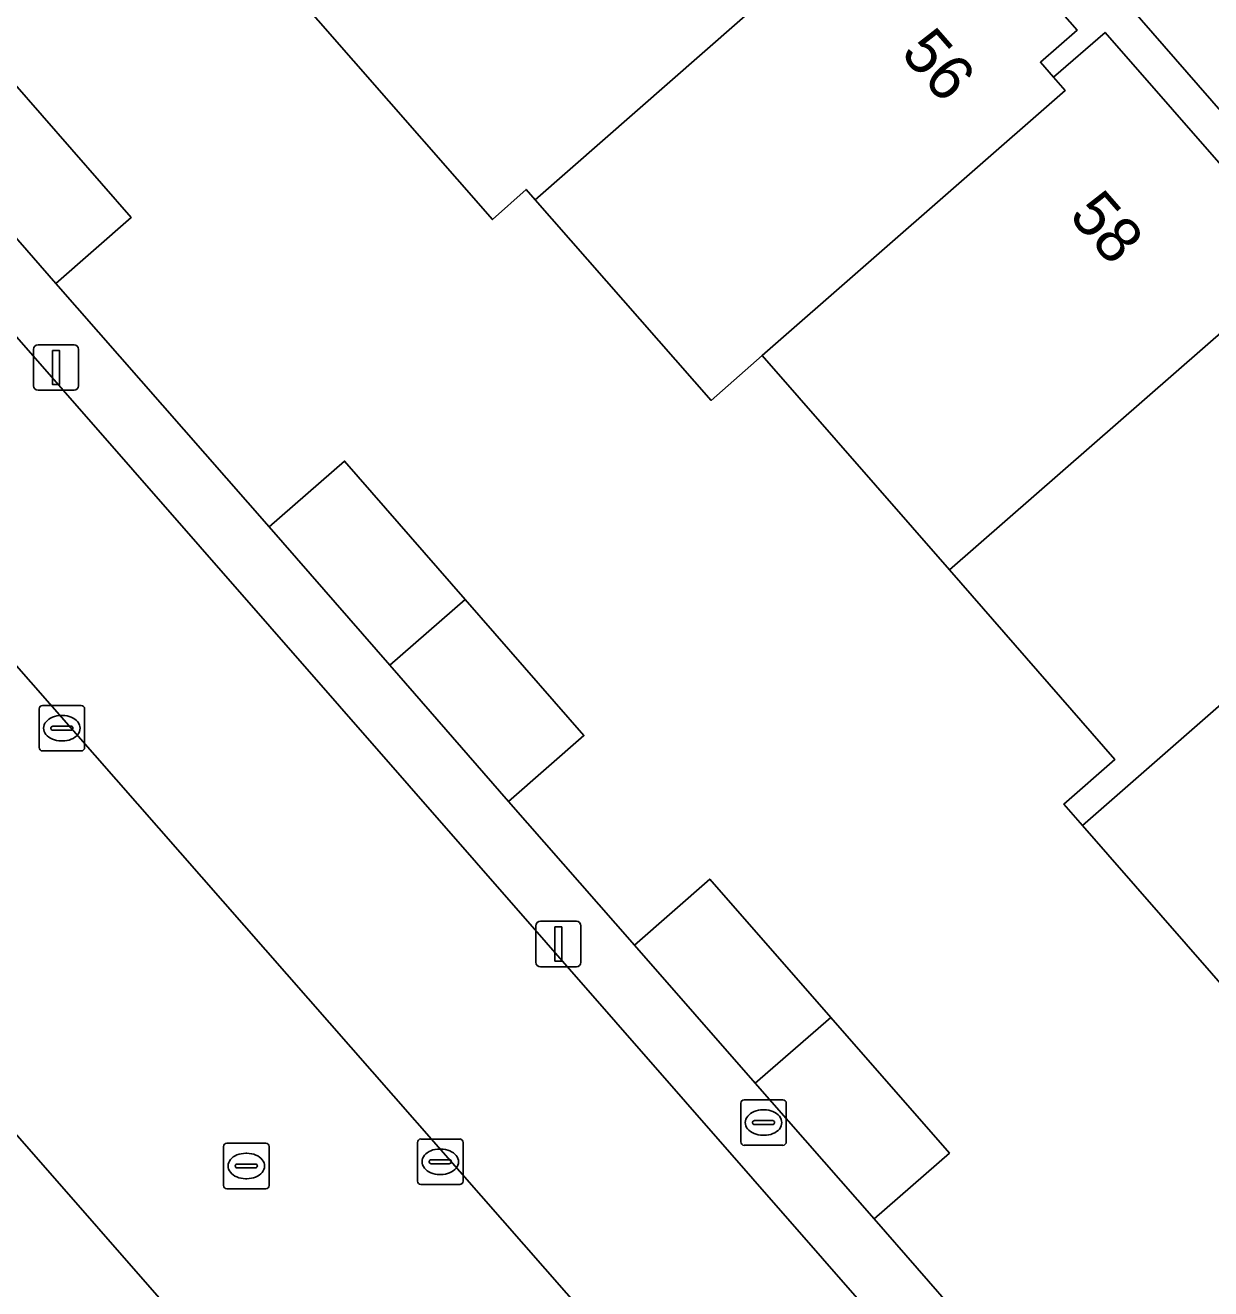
# Model space of a CAD drawing. Extents: x 161772 to 163126, y 383092 to 383917.
# Drawn here: x 162246.89 to 162272.95, y 383264.29 to 383292.04 of the extents above; entities that cross this region are included whole.
import ezdxf

# ---------------------------------------------------------------- set-up
doc = ezdxf.new("R2010")
doc.units = 0
for name, color, linetype in [('IMGEO_Erf', 7, 'Continuous'), ('IMGEO_Kolk', 7, 'Continuous'), ('IMGEO_Lichtmast', 7, 'Continuous'), ('IMGEO_Muur', 7, 'Continuous'), ('IMGEO_Pand', 7, 'Continuous'), ('IMGEO_Pand_nummerreeks', 7, 'Continuous'), ('IMGEO_Parkeervlak_gesloten', 7, 'Continuous'), ('IMGEO_Rijbaan_lokaal_gesloten', 7, 'Continuous'), ('IMGEO_Rioolput', 7, 'Continuous'), ('IMGEO_Voetpad_open', 7, 'Continuous')]:
    doc.layers.add(name, color=color, linetype=linetype)

msp = doc.modelspace()

# ---------------------------------------------------------------- linework, layer by layer
at = {"layer": 'IMGEO_Erf'}
for points in [[(162295.504, 383264.551), (162257.559, 383308.056)], [(162274.128, 383269.89), (162270.126, 383274.467), (162269.719, 383274.933), (162270.84, 383275.914), (162267.201, 383280.079), (162263.083, 383284.79), (162261.968, 383283.801), (162258.1, 383288.208), (162257.898, 383288.439), (162257.156, 383287.777), (162251.05, 383294.755)], [(162268.224, 383293.976), (162270.009, 383291.937), (162269.203, 383291.233), (162269.493, 383290.901), (162270.622, 383291.889), (162273.586, 383288.503)], [(162246.607, 383290.81), (162249.22, 383287.823), (162247.564, 383286.375), (162252.251, 383281.024), (162253.909, 383282.47), (162256.561, 383279.43), (162259.169, 383276.44), (162257.511, 383274.994), (162260.28, 383271.838), (162261.936, 383273.287), (162264.597, 383270.246), (162267.203, 383267.268), (162265.548, 383265.819), (162268.386, 383262.574), (162270.042, 383264.022), (162272.687, 383260.996), (162275.311, 383257.995)]]:
    msp.add_lwpolyline(points, dxfattribs=at)
at = {"layer": 'IMGEO_Kolk'}
for p, q in [((162247.194, 383276.175), (162247.194, 383277.027)), ((162247.269, 383277.101), (162248.121, 383277.101)), ((162248.195, 383277.027), (162248.195, 383276.175)), ((162247.682, 383276.881), (162247.707, 383276.881)), ((162247.453, 383276.595), (162247.453, 383276.607)), ((162247.891, 383276.558), (162247.493, 383276.558)), ((162247.496, 383276.644), (162247.894, 383276.644)), ((162247.937, 383276.607), (162247.937, 383276.595)), ((162247.705, 383276.321), (162247.68, 383276.321)), ((162248.121, 383276.101), (162247.269, 383276.101)), ((162262.691, 383268.437), (162263.543, 383268.437)), ((162262.616, 383267.511), (162262.616, 383268.363)), ((162263.104, 383268.217), (162263.129, 383268.217)), ((162263.617, 383268.363), (162263.617, 383267.511)), ((162262.875, 383267.931), (162262.875, 383267.943)), ((162263.313, 383267.894), (162262.915, 383267.894)), ((162262.918, 383267.98), (162263.316, 383267.98)), ((162263.359, 383267.943), (162263.359, 383267.931)), ((162263.127, 383267.657), (162263.102, 383267.657)), ((162255.511, 383266.65), (162255.511, 383267.502)), ((162255.586, 383267.576), (162256.438, 383267.576)), ((162255.999, 383267.356), (162256.024, 383267.356)), ((162256.512, 383267.502), (162256.512, 383266.65)), ((162263.543, 383267.437), (162262.691, 383267.437)), ((162255.77, 383267.07), (162255.77, 383267.082)), ((162256.208, 383267.033), (162255.81, 383267.033)), ((162255.813, 383267.119), (162256.211, 383267.119)), ((162256.254, 383267.082), (162256.254, 383267.07)), ((162256.022, 383266.796), (162255.997, 383266.796)), ((162256.438, 383266.576), (162255.586, 383266.576))]:
    msp.add_line(p, q, dxfattribs=at)
for points in [[(162247.194, 383276.175), (162247.194, 383277.027)], [(162247.269, 383277.101), (162248.121, 383277.101)], [(162248.195, 383277.027), (162248.195, 383276.175)], [(162248.121, 383276.101), (162247.269, 383276.101)], [(162262.691, 383268.437), (162263.543, 383268.437)], [(162262.616, 383267.511), (162262.616, 383268.363)], [(162263.617, 383268.363), (162263.617, 383267.511)], [(162255.511, 383266.65), (162255.511, 383267.502)], [(162255.586, 383267.576), (162256.438, 383267.576)], [(162256.512, 383267.502), (162256.512, 383266.65)], [(162263.543, 383267.437), (162262.691, 383267.437)], [(162256.438, 383266.576), (162255.586, 383266.576)]]:
    msp.add_lwpolyline(points, dxfattribs=at)
for centre, radius, start, end in [((162247.271, 383277.025), 0.0765, 91.552, 178.448), ((162247.271, 383277.025), 0.0765, 91.552, 178.448), ((162248.119, 383277.025), 0.0765, 1.552, 88.448), ((162248.119, 383277.025), 0.0765, 1.552, 88.448), ((162247.493, 383276.604), 0.0403, 85.8775, 175.7526), ((162247.49, 383276.594), 0.0366, 178.938, 274.7102), ((162247.894, 383276.601), 0.043, 264.8664, 352.4533), ((162247.898, 383276.606), 0.0386, 1.7309, 96.639), ((162247.271, 383276.177), 0.0765, 181.552, 268.448), ((162247.271, 383276.177), 0.0765, 181.552, 268.448), ((162248.119, 383276.177), 0.0765, 271.552, 358.448), ((162248.119, 383276.177), 0.0765, 271.552, 358.448), ((162262.693, 383268.361), 0.0765, 91.552, 178.448), ((162262.693, 383268.361), 0.0765, 91.552, 178.448), ((162263.541, 383268.361), 0.0765, 1.552, 88.448), ((162263.541, 383268.361), 0.0765, 1.552, 88.448), ((162262.915, 383267.94), 0.0403, 85.8775, 175.7526), ((162262.912, 383267.93), 0.0366, 178.938, 274.7102), ((162263.316, 383267.937), 0.043, 264.8664, 352.4533), ((162263.32, 383267.942), 0.0386, 1.7309, 96.639), ((162255.588, 383267.5), 0.0765, 91.552, 178.448), ((162255.588, 383267.5), 0.0765, 91.552, 178.448), ((162256.436, 383267.5), 0.0765, 1.552, 88.448), ((162256.436, 383267.5), 0.0765, 1.552, 88.448), ((162262.693, 383267.513), 0.0765, 181.552, 268.448), ((162262.693, 383267.513), 0.0765, 181.552, 268.448), ((162263.541, 383267.513), 0.0765, 271.552, 358.448), ((162263.541, 383267.513), 0.0765, 271.552, 358.448), ((162255.81, 383267.079), 0.0403, 85.8775, 175.7526), ((162255.807, 383267.069), 0.0366, 178.938, 274.7102), ((162256.211, 383267.076), 0.043, 264.8664, 352.4533), ((162256.215, 383267.081), 0.0386, 1.7309, 96.639), ((162255.588, 383266.652), 0.0765, 181.552, 268.448), ((162255.588, 383266.652), 0.0765, 181.552, 268.448), ((162256.436, 383266.652), 0.0765, 271.552, 358.448), ((162256.436, 383266.652), 0.0765, 271.552, 358.448)]:
    msp.add_arc(centre, radius, start, end, dxfattribs=at)
for centre, major_axis, ratio, start_param, end_param in [((162247.681, 383276.601), (-0.387, 0.002), 0.722429, 4.712389, 7.853982), ((162247.706, 383276.601), (-0.39, 0.002), 0.717154, 1.570796, 4.712389), ((162263.103, 383267.937), (-0.387, 0.002), 0.722429, 4.712389, 7.853982), ((162263.128, 383267.937), (-0.39, 0.002), 0.717154, 1.570796, 4.712389), ((162255.998, 383267.076), (-0.387, 0.002), 0.722429, 4.712389, 7.853982), ((162256.023, 383267.076), (-0.39, 0.002), 0.717154, 1.570796, 4.712389)]:
    msp.add_ellipse(centre, major_axis=major_axis, ratio=ratio, start_param=start_param, end_param=end_param, dxfattribs=at)
at = {"layer": 'IMGEO_Lichtmast'}
for p, q in [((162247.072, 383284.125), (162247.072, 383284.925)), ((162247.072, 383284.925), (162247.072, 383284.125)), ((162247.172, 383285.025), (162247.962, 383285.025)), ((162247.962, 383285.025), (162247.172, 383285.025)), ((162248.062, 383284.925), (162248.062, 383284.125)), ((162248.062, 383284.125), (162248.062, 383284.925)), ((162247.962, 383284.025), (162247.172, 383284.025)), ((162247.172, 383284.025), (162247.962, 383284.025)), ((162258.213, 383272.359), (162259.003, 383272.359)), ((162259.003, 383272.359), (162258.213, 383272.359)), ((162258.113, 383271.459), (162258.113, 383272.259)), ((162258.113, 383272.259), (162258.113, 383271.459)), ((162259.103, 383272.259), (162259.103, 383271.459)), ((162259.103, 383271.459), (162259.103, 383272.259)), ((162259.003, 383271.359), (162258.213, 383271.359)), ((162258.213, 383271.359), (162259.003, 383271.359))]:
    msp.add_line(p, q, dxfattribs=at)
for points in [[(162247.492, 383284.9), (162247.642, 383284.9), (162247.642, 383284.15), (162247.492, 383284.15), (162247.492, 383284.9)], [(162258.533, 383272.234), (162258.683, 383272.234), (162258.683, 383271.484), (162258.533, 383271.484), (162258.533, 383272.234)]]:
    msp.add_lwpolyline(points, dxfattribs=at)
for centre, start, end in [((162247.172, 383284.925), 90, 180), ((162247.172, 383284.925), 90, 180), ((162247.962, 383284.925), 0, 90), ((162247.962, 383284.925), 360, 90), ((162247.172, 383284.125), 180, 270), ((162247.172, 383284.125), 180, 270), ((162247.962, 383284.125), 270, 0), ((162247.962, 383284.125), 270, 0), ((162258.213, 383272.259), 90, 180), ((162258.213, 383272.259), 90, 180), ((162259.003, 383272.259), 0, 90), ((162259.003, 383272.259), 360, 90), ((162258.213, 383271.459), 180, 270), ((162258.213, 383271.459), 180, 270), ((162259.003, 383271.459), 270, 0), ((162259.003, 383271.459), 270, 0)]:
    msp.add_arc(centre, 0.1, start, end, dxfattribs=at)
at = {"layer": 'IMGEO_Muur'}
for points in [[(162252.251, 383281.024), (162247.564, 383286.375)], [(162260.28, 383271.838), (162257.511, 383274.994)], [(162268.386, 383262.574), (162265.548, 383265.819)]]:
    msp.add_lwpolyline(points, dxfattribs=at)
at = {"layer": 'IMGEO_Pand'}
for points in [[(162251.05, 383294.755), (162257.156, 383287.777), (162257.898, 383288.439), (162258.1, 383288.208), (162265.494, 383294.697), (162265.877, 383295.033), (162265.304, 383295.687), (162264.921, 383295.351), (162264.049, 383296.347), (162264.417, 383296.671), (162263.778, 383297.401), (162264.59, 383298.113), (162262.804, 383300.151), (162261.999, 383299.446), (162261.426, 383300.1), (162260.621, 383299.395), (162258.768, 383301.51)], [(162258.1, 383288.208), (162261.968, 383283.801), (162263.083, 383284.79), (162269.746, 383290.613), (162269.493, 383290.901), (162269.203, 383291.233), (162270.009, 383291.937), (162268.224, 383293.976), (162267.419, 383293.272), (162266.786, 383293.994), (162266.403, 383293.658), (162265.494, 383294.697)], [(162274.615, 383286.558), (162275, 383286.893), (162274.487, 383287.484), (162274.111, 383287.129), (162273.202, 383288.167), (162273.586, 383288.503), (162270.622, 383291.889), (162269.493, 383290.901), (162269.746, 383290.613), (162263.083, 383284.79), (162267.201, 383280.079)], [(162244.953, 383289.36), (162247.564, 383286.375), (162249.22, 383287.823), (162246.607, 383290.81)], [(162277.919, 383281.28), (162277.778, 383281.441), (162278.908, 383282.428), (162275.918, 383285.849), (162275.52, 383285.516), (162274.615, 383286.558), (162267.201, 383280.079), (162270.84, 383275.914), (162269.719, 383274.933), (162270.126, 383274.467)], [(162254.901, 383277.987), (162256.561, 383279.43), (162253.909, 383282.47), (162252.251, 383281.024)], [(162274.128, 383269.89), (162281.558, 383276.386), (162281.944, 383276.719), (162281.434, 383277.31), (162281.019, 383276.95), (162280.115, 383277.992), (162280.501, 383278.326), (162279.858, 383279.067), (162280.667, 383279.768), (162278.889, 383281.818), (162278.068, 383281.11), (162277.919, 383281.28), (162270.126, 383274.467)], [(162254.901, 383277.987), (162257.511, 383274.994), (162259.169, 383276.44), (162256.561, 383279.43)], [(162262.934, 383268.805), (162264.597, 383270.246), (162261.936, 383273.287), (162260.28, 383271.838)], [(162262.934, 383268.805), (162265.548, 383265.819), (162267.203, 383267.268), (162264.597, 383270.246)]]:
    msp.add_lwpolyline(points, close=True, dxfattribs=at)
at = {"layer": 'IMGEO_Parkeervlak_gesloten'}
for points in [[(162272.905, 383248.092), (162276.559, 383251.066), (162241.639, 383290.974), (162238.045, 383287.827)], [(162232.95, 383283.366), (162229.559, 383280.396), (162247.626, 383259.685), (162251.061, 383262.68)]]:
    msp.add_lwpolyline(points, close=True, dxfattribs=at)
at = {"layer": 'IMGEO_Rijbaan_lokaal_gesloten'}
msp.add_lwpolyline([(162251.061, 383262.68), (162252.791, 383260.692), (162249.275, 383257.833), (162248.076, 383256.871), (162241.074, 383251.163), (162244.227, 383247.286), (162252.554, 383254.049), (162256.096, 383256.95), (162257.613, 383255.216), (162267.579, 383243.756), (162272.905, 383248.092), (162238.045, 383287.827), (162232.95, 383283.366)], close=True, dxfattribs=at)
at = {"layer": 'IMGEO_Rioolput'}
for p, q in [((162251.248, 383266.557), (162251.248, 383267.409)), ((162251.323, 383267.483), (162252.175, 383267.483)), ((162252.249, 383267.409), (162252.249, 383266.557)), ((162251.736, 383267.263), (162251.761, 383267.263)), ((162251.507, 383266.977), (162251.507, 383266.989)), ((162251.945, 383266.94), (162251.547, 383266.94)), ((162251.55, 383267.026), (162251.948, 383267.026)), ((162251.991, 383266.989), (162251.991, 383266.977)), ((162252.175, 383266.483), (162251.323, 383266.483)), ((162251.759, 383266.703), (162251.734, 383266.703))]:
    msp.add_line(p, q, dxfattribs=at)
for points in [[(162251.248, 383266.557), (162251.248, 383267.409)], [(162251.323, 383267.483), (162252.175, 383267.483)], [(162252.249, 383267.409), (162252.249, 383266.557)], [(162252.175, 383266.483), (162251.323, 383266.483)]]:
    msp.add_lwpolyline(points, dxfattribs=at)
for centre, radius, start, end in [((162251.325, 383267.407), 0.0765, 91.552, 178.448), ((162251.325, 383267.407), 0.0765, 91.552, 178.448), ((162252.173, 383267.407), 0.0765, 1.552, 88.448), ((162252.173, 383267.407), 0.0765, 1.552, 88.448), ((162251.547, 383266.986), 0.0403, 85.8775, 175.7526), ((162251.544, 383266.976), 0.0366, 178.938, 274.7102), ((162251.948, 383266.983), 0.043, 264.8664, 352.4533), ((162251.952, 383266.988), 0.0386, 1.7309, 96.639), ((162251.325, 383266.559), 0.0765, 181.552, 268.448), ((162251.325, 383266.559), 0.0765, 181.552, 268.448), ((162252.173, 383266.559), 0.0765, 271.552, 358.448), ((162252.173, 383266.559), 0.0765, 271.552, 358.448)]:
    msp.add_arc(centre, radius, start, end, dxfattribs=at)
for centre, major_axis, ratio, start_param, end_param in [((162251.735, 383266.983), (-0.387, 0.002), 0.722429, 4.712389, 7.853982), ((162251.76, 383266.983), (-0.39, 0.002), 0.717154, 1.570796, 4.712389)]:
    msp.add_ellipse(centre, major_axis=major_axis, ratio=ratio, start_param=start_param, end_param=end_param, dxfattribs=at)
at = {"layer": 'IMGEO_Voetpad_open'}
for points in [[(162257.559, 383308.056), (162295.504, 383264.551), (162296.453, 383263.424), (162295.458, 383262.571), (162295.7, 383262.29), (162293.597, 383260.51), (162297.033, 383256.586), (162299.079, 383258.296), (162300.139, 383259.267), (162303.194, 383255.746), (162305.261, 383253.36), (162305.907, 383253.909), (162307.174, 383252.434), (162317.179, 383240.601), (162319.205, 383242.326), (162303.222, 383260.718)], [(162241.639, 383290.974), (162276.559, 383251.066), (162276.689, 383251.172), (162278.889, 383248.545), (162294.457, 383261.724), (162293.514, 383262.788), (162286.06, 383256.241), (162285.981, 383256.331), (162280.746, 383251.799), (162279.095, 383250.321), (162276.46, 383253.346), (162273.654, 383256.547), (162271.033, 383259.546), (162268.386, 383262.574), (162265.548, 383265.819), (162262.934, 383268.805), (162260.28, 383271.838), (162257.511, 383274.994), (162254.901, 383277.987), (162252.251, 383281.024), (162247.564, 383286.375), (162244.953, 383289.36)]]:
    msp.add_lwpolyline(points, dxfattribs=at)

# ---------------------------------------------------------------- texts
at = {"layer": 'IMGEO_Pand_nummerreeks'}
for s, rotation, p in [('56', 311.1949, (162266.106, 383291.416)), ('58', 311.2268, (162269.804, 383287.846))]:
    msp.add_text(s, height=1, rotation=rotation, dxfattribs=at).set_placement(p)

doc.saveas('drawing.dxf')
